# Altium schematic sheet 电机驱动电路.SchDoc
size A4
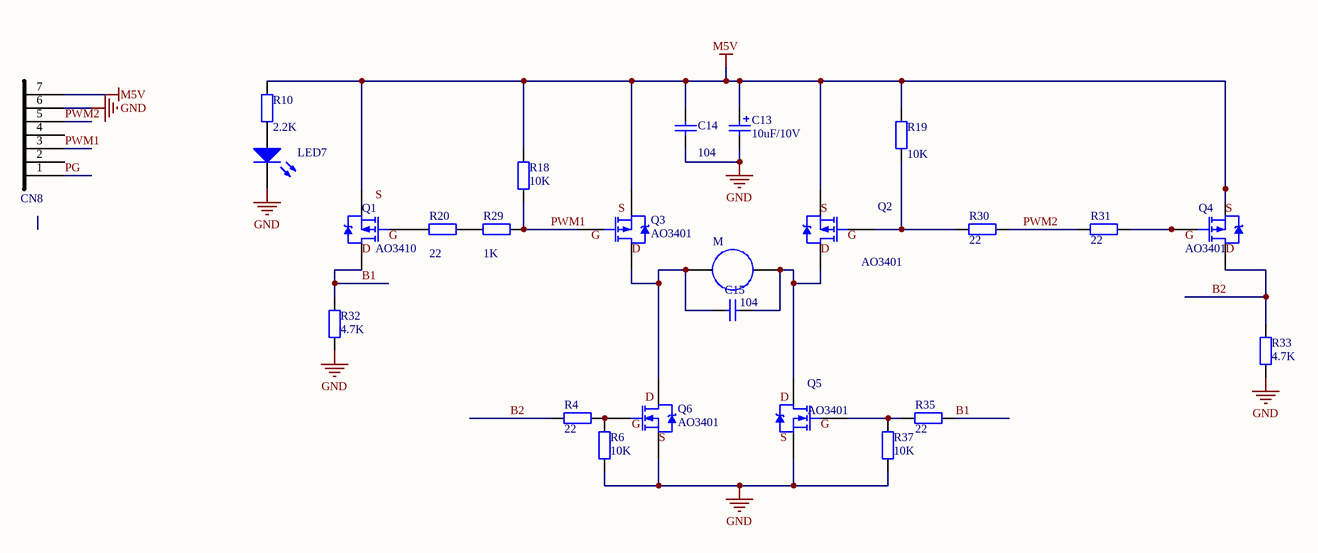
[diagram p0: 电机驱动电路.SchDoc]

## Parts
C13  value 10uF/10V  [6-0805_L]  (hidden comment: Cap Pol2)
C14  value 104  [6-0805_L]  (hidden comment: Cap)
C15  value 104  [6-0805_L]  (hidden comment: Cap)
CN8  Component_1  [HDR1X7]  (value not drawn)
LED7  LED0  [6-0805_L]  (value not drawn)
M  Meter  [RAD-0.1]  (value not drawn)
Q1  AO3410  [SOT-23B_L]
Q2  AO3401  [SOT-23B_L]
Q3  AO3401  [SOT-23B_L]
Q4  AO3401  [SOT-23B_L]
Q5  AO3401  [SOT-23B_L]
Q6  AO3401  [SOT-23B_L]
R4  value 22  [6-0805_L]  (hidden comment: Res2)
R6  value 10K  [6-0805_L]  (hidden comment: Res2)
R10  value 2.2K  [6-0805_L]  (hidden comment: Res2)
R18  value 10K  [6-0805_L]  (hidden comment: Res2)
R19  value 10K  [6-0805_L]  (hidden comment: Res2)
R20  value 22  [6-0805_L]  (hidden comment: Res2)
R29  value 1K  [6-0805_L]  (hidden comment: Res2)
R30  value 22  [6-0805_L]  (hidden comment: Res2)
R31  value 22  [6-0805_L]  (hidden comment: Res2)
R32  value 4.7K  [6-0805_L]  (hidden comment: Res2)
R33  value 4.7K  [6-0805_L]  (hidden comment: Res2)
R35  value 22  [6-0805_L]  (hidden comment: Res2)
R37  value 10K  [6-0805_L]  (hidden comment: Res2)

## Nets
GND: C13.2 C14.1 CN8.6 LED7.2(K) Q5.3(S) Q6.3(S) R6.2 R32.1 R33.1 R37.2
M5V: C13.1 C14.2 CN8.7 Q1.3(S) Q2.3(S) Q3.3(S) Q4.3(S) R10.2 R18.2 R19.2
B1: Q1.2(D) R32.2 R35.2
B2: Q4.2(D) R4.2 R33.2
PG: CN8.1
PWM1: CN8.3 Q3.1(G) R18.1 R29.2
PWM2: CN8.5 R30.2 R31.1
NetC15_1: C15.1 M.2 Q2.2(D) Q5.2(D)
NetC15_2: C15.2 M.1 Q3.2(D) Q6.2(D)
NetQ1_1: Q1.1(G) R20.1
NetQ2_1: Q2.1(G) R19.1 R30.1
NetQ4_1: Q4.1(G) R31.2
NetQ5_1: Q5.1(G) R35.1 R37.1
NetQ6_1: Q6.1(G) R4.1 R6.1
NetR20_2: R20.2 R29.1

Not connected (* = marked no-connect by the designer): CN8 2 4; LED7 1(A); R10 1

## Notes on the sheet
- Labels drawn without touching a wire or pin: D, G, S

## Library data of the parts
C13 = Cap Pol2: Polarized Capacitor (Axial)
C14 C15 = Cap: Capacitor
LED7 = LED0: Typical INFRARED GaAs LED
M = Meter: Indicating Instrument; Note: Place a "letter" into the symbol to show the function of the meter or instrument
Q1-Q4 = PMOS-2: P-Channel Power MOSFET; Note: Pin 4 not drawn and electrically connected to Pin 2.
Q5 Q6 = NMOS-2: N-Channel Power MOSFET; Note: Pin 2 is electrically connected to pin 4.
R4 R6 R10 R18-R20 R29-R33 R35 R37 = Res2: Resistor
